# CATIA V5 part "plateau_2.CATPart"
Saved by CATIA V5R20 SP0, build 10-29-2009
Part number: plateau_2
Publications: "plateau2_ecarth", "plateau2_H", "plateau2_l", "plateau2_h", "plateau2_pivotsup", "plateau2_pivotinf"
Bounding box of the stored display mesh (mm): x -10 to 110, y 50 to 400, z -50 to 100
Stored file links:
  C:\Users\Noëllie\Documents\IFMA\2A\S3\IAO\Projet Artobolevski\Catia\plateau_2.CATPart
  C:\Users\Noëllie\Documents\IFMA\2A\S3\IAO\Projet Artobolevski\Catia\Artobolevski 782.CATProduct
  C:\Users\Noëllie\Documents\IFMA\2A\S3\IAO\Projet Artobolevski\Catia\Squelette_general.CATPart
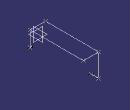
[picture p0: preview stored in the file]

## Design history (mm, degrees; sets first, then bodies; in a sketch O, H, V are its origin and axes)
Set1
  Point1 "C2": linked copy from another document
  Point2 "pp_21": linked copy from another document
  Point3 "B1d": linked copy from another document
  Point4 to Point7: linked copy from another document
Body1 (main body)
  Line1 "plateau2_h": type PtPt, FirstPoint Point2, SecondPoint Point3
  Line2 "plateau2_pivotsup": type PtDir, RefPoint Point3, Direction yz-plane, Start 10, End -10
  Line3 "plateau2_pivotinf": type PtDir, RefPoint Point1, Direction yz-plane, Start 10, End -10
  Line4 "plateau2_H": type PtPt, FirstPoint Point4, SecondPoint Point5
  Line5 "plateau2_eh": type PtPt, FirstPoint Point5, SecondPoint Point1
  Line6: type PtPt, FirstPoint Point2, SecondPoint Point6
  Line7: type PtPt, FirstPoint Point2, SecondPoint Point7
  Line8: type PtPt, FirstPoint Point7, SecondPoint Point4
  Line9: type PtPt, FirstPoint Point6, SecondPoint Point4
